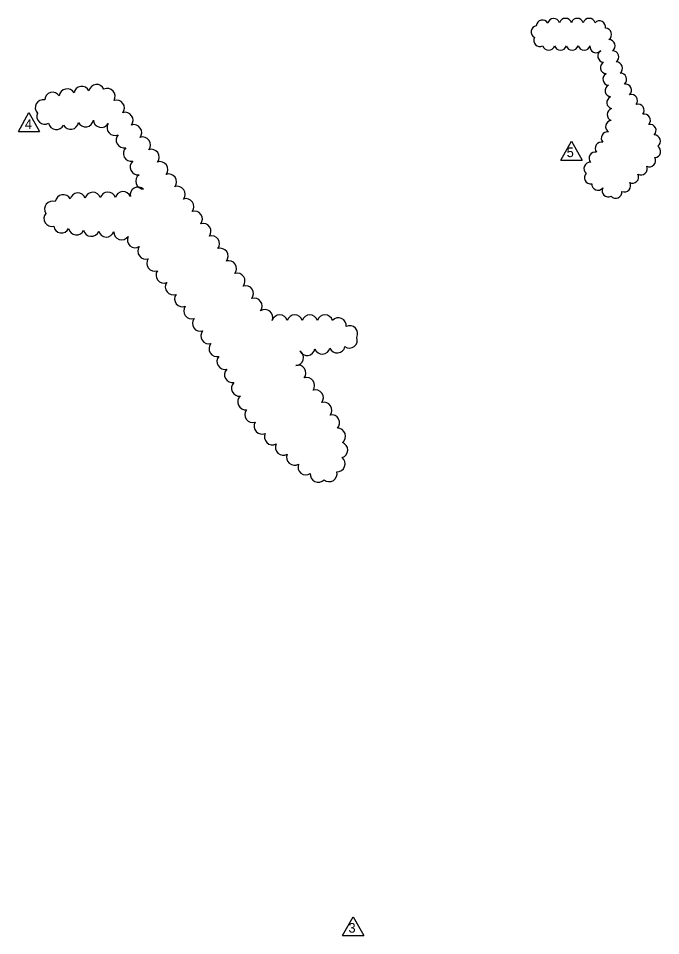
# Model space of a CAD drawing. Extents: x 1882804 to 1884487, y 844572 to 845443.
# Drawn here: x 1883543 to 1883942, y 844775 to 845346 of the extents above; entities that cross this region are included whole.
import ezdxf

# ---------------------------------------------------------------- set-up
doc = ezdxf.new("R2010")
doc.units = 0
doc.layers.add('Sheet Block Revision CELL', color=7, linetype='Continuous')

msp = doc.modelspace()

# ---------------------------------------------------------------- linework, layer by layer
at = {"layer": 'Sheet Block Revision CELL'}
for p, q in [((1883542.81, 845275.67), (1883549.39, 845287.43)), ((1883549.39, 845287.43), (1883556.05, 845275.72)), ((1883542.81, 845275.67), (1883556.05, 845275.72)), ((1883880.42, 845257.86), (1883886.99, 845269.62)), ((1883886.99, 845269.62), (1883893.66, 845257.91)), ((1883880.42, 845257.86), (1883893.66, 845257.91)), ((1883744.54, 844775.43), (1883751.12, 844787.19)), ((1883751.12, 844787.19), (1883757.78, 844775.48)), ((1883744.54, 844775.43), (1883757.78, 844775.48))]:
    msp.add_line(p, q, dxfattribs=at)
for centre, radius, start, end in [((1883868.95, 845341.1), 3.85, 30.5512, 175.5512), ((1883875.98, 845342.04), 3.85, 19.754, 164.754), ((1883883.27, 845342.18), 3.85, 17.5071, 162.5071), ((1883890.62, 845342.18), 3.85, 17.5, 162.5), ((1883897.96, 845342.18), 3.85, 17.5, 162.5), ((1883904.32, 845340.59), 3.85, 349.3585, 134.3585), ((1883865.69, 845337.59), 3.85, 98.5677, 243.5677), ((1883908.1, 845336.03), 3.85, 305.035, 90.035), ((1883867.38, 845332.34), 3.85, 152.0987, 297.0987), ((1883910.31, 845329.03), 3.85, 305.035, 90.035), ((1883872.8, 845330.06), 3.85, 197.3072, 342.3072), ((1883880.14, 845330.05), 3.85, 197.5, 342.5), ((1883887.48, 845330.05), 3.85, 197.5, 342.5), ((1883894.82, 845330.05), 3.85, 197.5, 342.5), ((1883902.32, 845328.46), 3.85, 173.5372, 318.5372), ((1883907.2, 845322.62), 3.85, 121.3221, 266.3221), ((1883912.54, 845322.03), 3.85, 305.3012, 90.3012), ((1883908.87, 845315.44), 3.85, 119.8498, 264.8498), ((1883914.89, 845315.04), 3.85, 306.8133, 91.8133), ((1883910.41, 845308.25), 3.85, 119.3697, 264.3697), ((1883917.48, 845308.12), 3.85, 309.2572, 94.2572), ((1883582.31, 845298.81), 4.92, 25.4829, 170.4829), ((1883591.58, 845299.97), 4.92, 23.7892, 168.7892), ((1883911.82, 845301.01), 3.85, 117.6133, 262.6133), ((1883920.5, 845301.34), 3.85, 313.6939, 98.6939), ((1883564.12, 845295.13), 4.92, 32.4745, 177.4745), ((1883573.16, 845297.25), 4.92, 28.9006, 173.9006), ((1883598.14, 845297.49), 4.92, 329.7462, 114.7462), ((1883912.81, 845293.65), 3.85, 112.7454, 257.7454), ((1883924.24, 845294.86), 3.85, 321.2908, 106.2908), ((1883558.26, 845290.52), 4.92, 78.9337, 223.9337), ((1883603.88, 845290.32), 4.92, 322.6712, 107.6712), ((1883928.31, 845288.76), 3.85, 321.0615, 106.0615), ((1883559.19, 845285.04), 4.92, 155.173, 300.173), ((1883609.28, 845282.66), 4.92, 322.6712, 107.6712), ((1883913.03, 845286.18), 3.85, 105.6199, 250.6199), ((1883932.25, 845282.61), 3.85, 319.3192, 104.3192), ((1883566.49, 845281.7), 4.92, 190.6405, 335.6405), ((1883575.34, 845281.93), 4.92, 207.3475, 352.3475), ((1883584.63, 845283.44), 4.92, 206.1246, 351.1246), ((1883594.39, 845283.09), 4.92, 184.7569, 329.7569), ((1883602.88, 845278.13), 4.92, 149.6769, 294.6769), ((1883614.68, 845274.99), 4.92, 322.6712, 107.6712), ((1883912.06, 845278.71), 3.85, 94.608, 239.608), ((1883935.78, 845276.3), 3.85, 314.1507, 99.1507), ((1883909.37, 845271.62), 3.85, 78.7837, 223.7837), ((1883608.55, 845270.33), 4.92, 137.3078, 282.3078), ((1883620.09, 845267.32), 4.92, 322.6712, 107.6712), ((1883905.59, 845265.24), 3.85, 74.9742, 219.9742), ((1883938.46, 845269.69), 3.85, 304.9848, 89.9848), ((1883613.09, 845262.06), 4.92, 135.2656, 280.2656), ((1883625.49, 845259.65), 4.92, 322.6712, 107.6712), ((1883901.75, 845259.02), 3.85, 76.612, 221.612), ((1883938.63, 845263.27), 3.85, 273.0145, 58.0145), ((1883617.31, 845253.62), 4.92, 132.867, 277.867), ((1883630.89, 845251.98), 4.92, 322.6599, 107.6599), ((1883935.47, 845257.55), 3.85, 244.1441, 29.1441), ((1883898.57, 845252.63), 3.85, 85.5429, 230.5429), ((1883930.29, 845252.5), 3.85, 239.3787, 24.3787), ((1883620.76, 845244.69), 4.92, 124.3827, 269.3827), ((1883636.29, 845244.31), 4.92, 322.602, 107.602), ((1883898.88, 845246.96), 3.85, 135.584, 280.584), ((1883924.93, 845247.37), 3.85, 243.1795, 28.1795), ((1883617.36, 845236.17), 4.92, 47.0123, 192.0123), ((1883641.68, 845236.64), 4.92, 322.5309, 107.5309), ((1883903.43, 845242.96), 3.85, 176.7583, 321.7583), ((1883909.87, 845238.82), 3.85, 152.7321, 297.7321), ((1883919.91, 845241.94), 3.85, 246.2799, 31.2799), ((1883570.7, 845231.4), 4.92, 27.349, 172.349), ((1883579.84, 845232.49), 4.92, 21.2186, 166.2186), ((1883589.16, 845232.91), 4.92, 18.9869, 163.9869), ((1883598.51, 845233.06), 4.92, 17.8673, 162.8673), ((1883607.96, 845233.38), 4.92, 21.0229, 166.0229), ((1883914.54, 845237.97), 3.85, 221.6581, 6.6581), ((1883564.07, 845227.46), 4.92, 69.0266, 214.0266), ((1883647.06, 845228.95), 4.92, 322.4483, 107.4483), ((1883563.68, 845221.47), 4.92, 138.7154, 283.7154), ((1883652.42, 845221.26), 4.92, 322.3506, 107.3506), ((1883657.77, 845213.56), 4.92, 322.2326, 107.2326), ((1883569.71, 845217.44), 4.92, 188.7185, 333.7185), ((1883578.95, 845216.21), 4.92, 191.1828, 336.1828), ((1883588.23, 845215.38), 4.92, 193.5197, 338.5197), ((1883597.53, 845214.93), 4.92, 195.9911, 340.9911), ((1883607.1, 845213.22), 4.92, 178.7047, 323.7047), ((1883615.54, 845208.27), 4.92, 155.5881, 300.5881), ((1883663.1, 845205.85), 4.92, 322.0861, 107.0861), ((1883622.04, 845201.18), 4.92, 144.3767, 289.3767), ((1883668.41, 845198.12), 4.92, 321.8974, 106.8974), ((1883627.68, 845193.69), 4.92, 144.6907, 289.6907), ((1883673.69, 845190.38), 4.92, 321.6411, 106.6411), ((1883633.39, 845186.27), 4.92, 145.4515, 290.4515), ((1883678.93, 845182.6), 4.92, 321.313, 106.313), ((1883639.19, 845178.92), 4.92, 146.0539, 291.0539), ((1883684.19, 845174.82), 4.92, 321.7744, 106.7744), ((1883644.99, 845171.52), 4.92, 145.1794, 290.1794), ((1883689.59, 845167.11), 4.92, 323.2108, 108.2108), ((1883650.64, 845163.98), 4.92, 143.4482, 288.4482), ((1883696.19, 845160.03), 4.92, 337.7701, 122.7701), ((1883705.43, 845156.69), 4.92, 17.5, 162.5), ((1883714.81, 845156.69), 4.92, 17.5, 162.5), ((1883724.19, 845156.69), 4.92, 17.5, 162.5), ((1883733.57, 845156.67), 4.92, 17.3847, 162.3847), ((1883656.07, 845156.28), 4.92, 141.9785, 286.9785), ((1883741.92, 845154.86), 4.91, 352.9909, 137.9909), ((1883749.06, 845149.89), 4.92, 332.374, 117.374), ((1883661.31, 845148.47), 4.92, 140.7128, 285.7128), ((1883666.39, 845140.55), 4.92, 139.6034, 284.6034), ((1883748.82, 845145.87), 4.91, 235.666, 20.666), ((1883715.33, 845134.99), 4.92, 271.2638, 56.2638), ((1883722.5, 845141.2), 4.92, 205.5063, 350.5063), ((1883731.95, 845142.13), 4.92, 200.771, 345.771), ((1883741.24, 845142.84), 4.92, 202.9408, 347.9408), ((1883671.31, 845132.52), 4.92, 138.3836, 283.3836), ((1883676.01, 845124.35), 4.92, 136.5297, 281.5297), ((1883716.86, 845125.37), 4.92, 321.8378, 106.8378), ((1883722.25, 845117.66), 4.92, 323.0093, 108.0093), ((1883680.36, 845115.94), 4.92, 133.1082, 278.1082), ((1883727.71, 845110.02), 4.92, 323.1598, 108.1598), ((1883684.28, 845107.37), 4.92, 131.0339, 276.0339), ((1883733, 845102.35), 4.92, 320.9693, 105.9693), ((1883688.69, 845099.48), 4.92, 142.4179, 287.4179), ((1883737.81, 845094.43), 4.92, 316.6657, 101.6657), ((1883694.41, 845092.3), 4.92, 149.6301, 294.6301), ((1883700.86, 845085.64), 4.92, 153.5895, 298.5895), ((1883741.51, 845086.14), 4.92, 306.4153, 91.4153), ((1883707.66, 845079.22), 4.92, 154.7462, 299.7462), ((1883742.86, 845077.52), 4.92, 286.4049, 71.4049), ((1883714.6, 845072.97), 4.92, 156.1637, 301.1637), ((1883721.74, 845067), 4.92, 159.0683, 304.0683), ((1883741.23, 845068.93), 4.92, 267.0986, 52.0986), ((1883729.38, 845062.33), 4.92, 173.0057, 318.0057), ((1883736.22, 845062.78), 4.92, 229.5492, 14.5492)]:
    msp.add_arc(centre, radius, start, end, dxfattribs=at)

# ---------------------------------------------------------------- texts
for s, p in [('4', (1883546.85, 845277.23)), ('5', (1883884, 845259.7)), ('3', (1883748.22, 844777.27))]:
    msp.add_text(s, height=6, rotation=0.2208, dxfattribs=at).set_placement(p)

doc.saveas('drawing.dxf')
